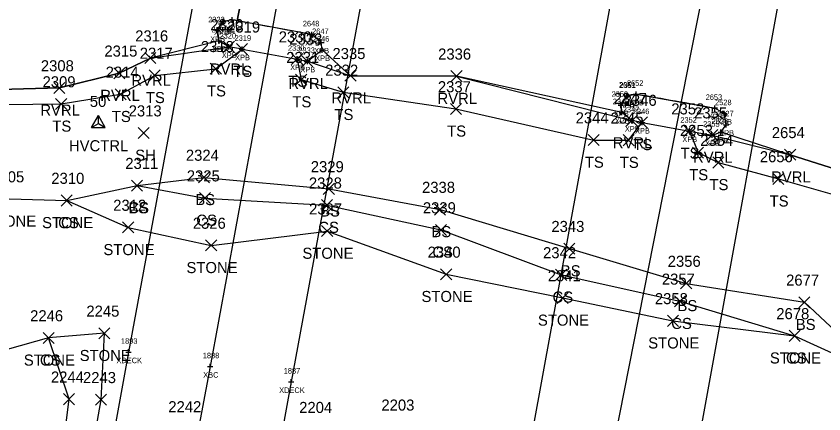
# Model space of a CAD drawing. Extents: x 1472022 to 1479249, y 777216 to 786527.
# Drawn here: x 1473550.5 to 1473696.2, y 779396.3 to 779468.1 of the extents above; entities that cross this region are included whole.
import ezdxf

# ---------------------------------------------------------------- set-up
doc = ezdxf.new("R2010")
doc.units = 0
for name, color, linetype in [('B_A', 7, 'Continuous'), ('B_I', 7, 'Continuous'), ('B_TIC', 7, 'Continuous'), ('BELB', 7, 'Continuous'), ('BSUBM', 7, 'Continuous'), ('C_A', 7, 'Continuous'), ('C_I', 7, 'Continuous'), ('CPSM', 7, 'Continuous'), ('L_A', 7, 'Continuous'), ('L_I', 7, 'Continuous'), ('L_TIC', 7, 'Continuous'), ('LASF', 7, 'Continuous'), ('LAWE', 7, 'Continuous'), ('LELB', 7, 'Continuous'), ('LSOGP', 7, 'Continuous')]:
    doc.layers.add(name, color=color, linetype=linetype)

msp = doc.modelspace()

# ---------------------------------------------------------------- linework, layer by layer
at = {"layer": 'B_TIC'}
for p, q in [((1473589.52, 779467.42), (1473589.6, 779467.42)), ((1473587.5, 779466.72), (1473587.58, 779466.72)), ((1473587.92, 779467.15), (1473587.99, 779467.15)), ((1473587.92, 779467.15), (1473587.99, 779467.15)), ((1473586.8, 779465.48), (1473586.87, 779465.48)), ((1473603.9, 779464.76), (1473603.97, 779464.76)), ((1473587.11, 779463.65), (1473587.19, 779463.65)), ((1473605.57, 779463.37), (1473605.64, 779463.37)), ((1473588.89, 779462.56), (1473588.97, 779462.56)), ((1473591.28, 779462.14), (1473591.36, 779462.14)), ((1473591.28, 779462.14), (1473591.36, 779462.14)), ((1473605.73, 779462), (1473605.8, 779462)), ((1473601.23, 779460.35), (1473601.3, 779460.35)), ((1473603.06, 779459.95), (1473603.14, 779459.95)), ((1473660.63, 779453.72), (1473660.71, 779453.72)), ((1473660.7, 779453.62), (1473660.78, 779453.62)), ((1473662.36, 779454.02), (1473662.43, 779454.02)), ((1473659.61, 779452.04), (1473659.69, 779452.04)), ((1473676.56, 779451.47), (1473676.63, 779451.47)), ((1473676.56, 779451.47), (1473676.63, 779451.47)), ((1473659.78, 779450.7), (1473659.86, 779450.7)), ((1473678.23, 779450.53), (1473678.31, 779450.53)), ((1473661.6, 779449.25), (1473661.67, 779449.25)), ((1473663.43, 779448.91), (1473663.51, 779448.91)), ((1473663.43, 779448.91), (1473663.51, 779448.91)), ((1473678.61, 779448.51), (1473678.68, 779448.51)), ((1473671.96, 779447.36), (1473672.04, 779447.36)), ((1473677.66, 779447.13), (1473677.74, 779447.13)), ((1473676.07, 779446.64), (1473676.14, 779446.64)), ((1473570.78, 779407.46), (1473570.86, 779407.46)), ((1473585.54, 779404.85), (1473585.61, 779404.85)), ((1473600.14, 779402.08), (1473600.21, 779402.08))]:
    msp.add_line(p, q, dxfattribs=at)
for points in [[(1473587.91, 779466.65), (1473587.91, 779467.65)], [(1473587.91, 779466.65), (1473587.91, 779467.65)], [(1473589.02, 779467.42), (1473590.02, 779467.42)], [(1473589.52, 779466.92), (1473589.52, 779467.92)], [(1473586.8, 779464.98), (1473586.8, 779465.98)], [(1473587, 779466.72), (1473588, 779466.72)], [(1473587.41, 779467.15), (1473588.41, 779467.15)], [(1473587.41, 779467.15), (1473588.41, 779467.15)], [(1473587.5, 779466.22), (1473587.5, 779467.22)], [(1473586.3, 779465.48), (1473587.3, 779465.48)], [(1473603.39, 779464.76), (1473604.39, 779464.76)], [(1473603.89, 779464.26), (1473603.89, 779465.26)], [(1473586.61, 779463.65), (1473587.61, 779463.65)], [(1473587.11, 779463.15), (1473587.11, 779464.15)], [(1473588.89, 779462.06), (1473588.89, 779463.06)], [(1473605.07, 779463.37), (1473606.07, 779463.37)], [(1473605.57, 779462.87), (1473605.57, 779463.87)], [(1473588.39, 779462.56), (1473589.39, 779462.56)], [(1473590.78, 779462.14), (1473591.78, 779462.14)], [(1473590.78, 779462.14), (1473591.78, 779462.14)], [(1473591.28, 779461.64), (1473591.28, 779462.64)], [(1473591.28, 779461.64), (1473591.28, 779462.64)], [(1473605.22, 779462), (1473606.22, 779462)], [(1473605.72, 779461.5), (1473605.72, 779462.5)], [(1473600.72, 779460.35), (1473601.72, 779460.35)], [(1473601.22, 779459.85), (1473601.22, 779460.85)], [(1473603.06, 779459.45), (1473603.06, 779460.45)], [(1473602.56, 779459.95), (1473603.56, 779459.95)], [(1473660.63, 779453.22), (1473660.63, 779454.22)], [(1473662.35, 779453.52), (1473662.35, 779454.52)], [(1473660.13, 779453.72), (1473661.13, 779453.72)], [(1473660.2, 779453.62), (1473661.2, 779453.62)], [(1473660.7, 779453.12), (1473660.7, 779454.12)], [(1473661.85, 779454.02), (1473662.85, 779454.02)], [(1473659.11, 779452.04), (1473660.11, 779452.04)], [(1473659.61, 779451.54), (1473659.61, 779452.54)], [(1473676.06, 779451.47), (1473677.06, 779451.47)], [(1473676.06, 779451.47), (1473677.06, 779451.47)], [(1473676.56, 779450.97), (1473676.56, 779451.97)], [(1473676.56, 779450.97), (1473676.56, 779451.97)], [(1473659.28, 779450.7), (1473660.28, 779450.7)], [(1473659.78, 779450.2), (1473659.78, 779451.2)], [(1473677.73, 779450.53), (1473678.73, 779450.53)], [(1473678.23, 779450.03), (1473678.23, 779451.03)], [(1473661.09, 779449.25), (1473662.09, 779449.25)], [(1473661.59, 779448.75), (1473661.59, 779449.75)], [(1473662.93, 779448.91), (1473663.93, 779448.91)], [(1473662.93, 779448.91), (1473663.93, 779448.91)], [(1473663.43, 779448.41), (1473663.43, 779449.41)], [(1473663.43, 779448.41), (1473663.43, 779449.41)], [(1473678.1, 779448.51), (1473679.1, 779448.51)], [(1473678.6, 779448.01), (1473678.6, 779449.01)], [(1473671.46, 779447.36), (1473672.46, 779447.36)], [(1473671.96, 779446.86), (1473671.96, 779447.86)], [(1473676.07, 779446.14), (1473676.07, 779447.14)], [(1473677.16, 779447.13), (1473678.16, 779447.13)], [(1473677.66, 779446.63), (1473677.66, 779447.63)], [(1473675.57, 779446.64), (1473676.57, 779446.64)], [(1473570.78, 779406.96), (1473570.78, 779407.96)], [(1473570.28, 779407.46), (1473571.28, 779407.46)], [(1473585.03, 779404.85), (1473586.03, 779404.85)], [(1473585.53, 779404.35), (1473585.53, 779405.35)], [(1473599.63, 779402.08), (1473600.63, 779402.08)], [(1473600.13, 779401.58), (1473600.13, 779402.58)]]:
    msp.add_lwpolyline(points, dxfattribs=at)
at = {"layer": 'BELB'}
for points in [[(1473646.9, 779823.47), (1473635.72, 779761.4), (1473617.71, 779663.02), (1473604.51, 779591.79), (1473588.93, 779505.83), (1473570.78, 779407.46), (1473559.55, 779345.54)], [(1473663.54, 779820.45), (1473650.78, 779758.62), (1473632.81, 779660.5), (1473616.07, 779571.01), (1473603.54, 779503.11), (1473585.53, 779404.85), (1473573.79, 779342.6)], [(1473676.24, 779818.18), (1473665.15, 779756.22), (1473647.13, 779657.83), (1473630.64, 779568.27), (1473618.22, 779500.38), (1473600.13, 779402.08), (1473588.74, 779339.91)], [(1473632.64, 779331.64), (1473643.77, 779393.67), (1473661.77, 779492.35), (1473674.97, 779565.3), (1473690.2, 779649.78), (1473708.22, 779748.21)], [(1473648.23, 779328.95), (1473658.53, 779391.7), (1473677.73, 779489.35), (1473690.33, 779561.53), (1473706.17, 779646.87), (1473724.09, 779745.09)], [(1473662.07, 779326.37), (1473673.18, 779388.74), (1473691.04, 779487.09), (1473704.3, 779559.92), (1473719.46, 779644.73), (1473737.38, 779742.92)]]:
    msp.add_lwpolyline(points, dxfattribs=at)
at = {"layer": 'BSUBM'}
for points in [[(1473591.28, 779462.14), (1473601.22, 779460.35), (1473603.06, 779459.95), (1473605.72, 779462), (1473605.57, 779463.37), (1473603.89, 779464.76), (1473589.52, 779467.42), (1473587.91, 779467.15)], [(1473591.28, 779462.14), (1473588.89, 779462.56), (1473587.11, 779463.65), (1473586.8, 779465.48), (1473587.5, 779466.72), (1473587.91, 779467.15)], [(1473663.43, 779448.91), (1473661.59, 779449.25), (1473659.78, 779450.7), (1473659.61, 779452.04), (1473660.7, 779453.62), (1473660.63, 779453.72), (1473662.35, 779454.02), (1473676.56, 779451.47)], [(1473663.43, 779448.91), (1473671.96, 779447.36), (1473676.07, 779446.64), (1473677.66, 779447.13), (1473678.6, 779448.51), (1473678.23, 779450.53), (1473676.56, 779451.47)]]:
    msp.add_lwpolyline(points, dxfattribs=at)
at = {"layer": 'CPSM'}
for p, q in [((1473564.11, 779447.99), (1473565.36, 779450.15)), ((1473566.61, 779447.99), (1473565.36, 779450.15)), ((1473565.36, 779448.71), (1473565.36, 779450.15)), ((1473564.11, 779447.99), (1473565.36, 779448.71)), ((1473565.36, 779448.71), (1473565.36, 779448.71)), ((1473565.36, 779448.71), (1473566.61, 779447.99)), ((1473564.11, 779447.99), (1473566.61, 779447.99))]:
    msp.add_line(p, q, dxfattribs=at)
at = {"layer": 'L_TIC'}
for points in [[(1473587.89, 779461.56), (1473589.89, 779463.56)], [(1473589.89, 779461.56), (1473587.89, 779463.56)], [(1473590.28, 779461.14), (1473592.28, 779463.14)], [(1473592.28, 779461.14), (1473590.28, 779463.14)], [(1473573.75, 779459.53), (1473575.75, 779461.53)], [(1473575.75, 779459.53), (1473573.75, 779461.53)], [(1473600.22, 779459.35), (1473602.22, 779461.35)], [(1473602.22, 779459.35), (1473600.22, 779461.35)], [(1473602.06, 779458.95), (1473604.06, 779460.95)], [(1473604.06, 779458.95), (1473602.06, 779460.95)], [(1473568.13, 779456.8), (1473570.13, 779458.8)], [(1473570.13, 779456.8), (1473568.13, 779458.8)], [(1473585.54, 779457.61), (1473587.54, 779459.61)], [(1473587.54, 779457.61), (1473585.54, 779459.61)], [(1473574.52, 779456.41), (1473576.52, 779458.41)], [(1473576.52, 779456.41), (1473574.52, 779458.41)], [(1473600.94, 779455.64), (1473602.94, 779457.64)], [(1473602.94, 779455.64), (1473600.94, 779457.64)], [(1473609.84, 779456.35), (1473611.84, 779458.35)], [(1473611.84, 779456.35), (1473609.84, 779458.35)], [(1473628.96, 779456.26), (1473630.96, 779458.26)], [(1473630.96, 779456.26), (1473628.96, 779458.26)], [(1473557.32, 779454.14), (1473559.32, 779456.14)], [(1473559.32, 779454.14), (1473557.32, 779456.14)], [(1473568.37, 779452.99), (1473570.37, 779454.99)], [(1473570.37, 779452.99), (1473568.37, 779454.99)], [(1473608.53, 779453.35), (1473610.53, 779455.35)], [(1473610.53, 779453.35), (1473608.53, 779455.35)], [(1473557.64, 779451.25), (1473559.64, 779453.25)], [(1473559.64, 779451.25), (1473557.64, 779453.25)], [(1473628.86, 779450.36), (1473630.86, 779452.36)], [(1473630.86, 779450.36), (1473628.86, 779452.36)], [(1473660.59, 779448.25), (1473662.59, 779450.25)], [(1473662.59, 779448.25), (1473660.59, 779450.25)], [(1473662.43, 779447.91), (1473664.43, 779449.91)], [(1473664.43, 779447.91), (1473662.43, 779449.91)], [(1473670.96, 779446.36), (1473672.96, 779448.36)], [(1473672.96, 779446.36), (1473670.96, 779448.36)], [(1473572.51, 779446), (1473574.51, 779448)], [(1473574.51, 779446), (1473572.51, 779448)], [(1473675.07, 779445.64), (1473677.07, 779447.64)], [(1473677.07, 779445.64), (1473675.07, 779447.64)], [(1473653.71, 779444.74), (1473655.71, 779446.74)], [(1473655.71, 779444.74), (1473653.71, 779446.74)], [(1473660, 779444.71), (1473662, 779446.71)], [(1473662, 779444.71), (1473660, 779446.71)], [(1473672.52, 779442.48), (1473674.52, 779444.48)], [(1473674.52, 779442.48), (1473672.52, 779444.48)], [(1473689.14, 779442.08), (1473691.14, 779444.08)], [(1473691.14, 779442.08), (1473689.14, 779444.08)], [(1473676.18, 779440.69), (1473678.18, 779442.69)], [(1473678.18, 779440.69), (1473676.18, 779442.69)], [(1473583.4, 779437.99), (1473585.4, 779439.99)], [(1473585.4, 779437.99), (1473583.4, 779439.99)], [(1473687.03, 779437.73), (1473689.03, 779439.73)], [(1473689.03, 779437.73), (1473687.03, 779439.73)], [(1473571.34, 779436.52), (1473573.34, 779438.52)], [(1473573.34, 779436.52), (1473571.34, 779438.52)], [(1473571.34, 779436.52), (1473573.34, 779438.52)], [(1473573.34, 779436.52), (1473571.34, 779438.52)], [(1473605.93, 779435.93), (1473607.93, 779437.93)], [(1473607.93, 779435.93), (1473605.93, 779437.93)], [(1473558.65, 779433.83), (1473560.65, 779435.83)], [(1473560.65, 779433.83), (1473558.65, 779435.83)], [(1473558.65, 779433.83), (1473560.65, 779435.83)], [(1473560.65, 779433.83), (1473558.65, 779435.83)], [(1473583.57, 779434.27), (1473585.57, 779436.27)], [(1473585.57, 779434.27), (1473583.57, 779436.27)], [(1473605.59, 779432.98), (1473607.59, 779434.98)], [(1473607.59, 779432.98), (1473605.59, 779434.98)], [(1473626, 779432.2), (1473628, 779434.2)], [(1473628, 779432.2), (1473626, 779434.2)], [(1473569.73, 779428.96), (1473571.73, 779430.96)], [(1473571.73, 779428.96), (1473569.73, 779430.96)], [(1473605.62, 779428.3), (1473607.62, 779430.3)], [(1473607.62, 779428.3), (1473605.62, 779430.3)], [(1473626.15, 779428.51), (1473628.15, 779430.51)], [(1473628.15, 779428.51), (1473626.15, 779430.51)], [(1473584.71, 779425.72), (1473586.71, 779427.72)], [(1473586.71, 779425.72), (1473584.71, 779427.72)], [(1473649.33, 779425.14), (1473651.33, 779427.14)], [(1473651.33, 779425.14), (1473649.33, 779427.14)], [(1473627.1, 779420.5), (1473629.1, 779422.5)], [(1473629.1, 779420.5), (1473627.1, 779422.5)], [(1473647.83, 779420.4), (1473649.83, 779422.4)], [(1473649.83, 779420.4), (1473647.83, 779422.4)], [(1473670.38, 779418.85), (1473672.38, 779420.85)], [(1473672.38, 779418.85), (1473670.38, 779420.85)], [(1473648.11, 779416.23), (1473650.11, 779418.23)], [(1473650.11, 779416.23), (1473648.11, 779418.23)], [(1473669.26, 779415.63), (1473671.26, 779417.63)], [(1473671.26, 779415.63), (1473669.26, 779417.63)], [(1473691.72, 779415.45), (1473693.72, 779417.45)], [(1473693.72, 779415.45), (1473691.72, 779417.45)], [(1473668, 779412.11), (1473670, 779414.11)], [(1473670, 779412.11), (1473668, 779414.11)], [(1473555.37, 779409.02), (1473557.37, 779411.02)], [(1473557.37, 779409.02), (1473555.37, 779411.02)], [(1473555.37, 779409.02), (1473557.37, 779411.02)], [(1473557.37, 779409.02), (1473555.37, 779411.02)], [(1473565.45, 779409.85), (1473567.45, 779411.85)], [(1473567.45, 779409.85), (1473565.45, 779411.85)], [(1473689.95, 779409.4), (1473691.95, 779411.4)], [(1473691.95, 779409.4), (1473689.95, 779411.4)], [(1473689.95, 779409.4), (1473691.95, 779411.4)], [(1473691.95, 779409.4), (1473689.95, 779411.4)], [(1473559.06, 779397.96), (1473561.06, 779399.96)], [(1473561.06, 779397.96), (1473559.06, 779399.96)], [(1473564.84, 779397.86), (1473566.84, 779399.86)], [(1473566.84, 779397.86), (1473564.84, 779399.86)]]:
    msp.add_lwpolyline(points, dxfattribs=at)
at = {"layer": 'LASF'}
for points in [[(1473473.27, 779398.69), (1473490.14, 779416.95), (1473498.08, 779421.83), (1473506.81, 779422.34), (1473517.64, 779423.49), (1473523.38, 779426.73), (1473532.1, 779433.42), (1473538.27, 779434.84), (1473549.37, 779435.1), (1473559.65, 779434.83), (1473570.73, 779429.96), (1473585.71, 779426.72), (1473606.62, 779429.3), (1473628.1, 779421.5), (1473649.11, 779417.23), (1473669, 779413.11), (1473690.95, 779410.4), (1473712.68, 779400.49)], [(1473633.09, 779342.06), (1473637.36, 779354.76), (1473634.83, 779370.15), (1473634.39, 779386.13), (1473619.75, 779393.9), (1473604.91, 779393.47), (1473602.82, 779381.23), (1473597.4, 779362.46), (1473593.63, 779347.94), (1473579.62, 779350.93), (1473559.31, 779355.6), (1473561.08, 779365.73), (1473563.08, 779383.25), (1473565.84, 779398.86), (1473566.45, 779410.85), (1473556.37, 779410.02), (1473539.02, 779405.15), (1473523.92, 779401.84), (1473511.03, 779390.76), (1473502.06, 779373.78), (1473492.39, 779361.71)]]:
    msp.add_lwpolyline(points, dxfattribs=at)
at = {"layer": 'LAWE'}
for points in [[(1473463.64, 779459.86), (1473474.22, 779451.75), (1473490.1, 779450.63), (1473502.38, 779450.61), (1473513.03, 779446.48), (1473521.87, 779448.87), (1473523.28, 779449.82), (1473531, 779452.15), (1473543.2, 779454.75), (1473558.32, 779455.14), (1473569.13, 779457.8), (1473574.75, 779460.53), (1473588.89, 779462.56)], [(1473603.06, 779459.95), (1473610.84, 779457.35), (1473629.96, 779457.26), (1473661.59, 779449.25)], [(1473676.07, 779446.64), (1473690.14, 779443.08), (1473702.13, 779439.28), (1473717.49, 779433.42), (1473726.6, 779424.72), (1473742.11, 779423.68), (1473761.32, 779420.04), (1473781.68, 779418.82), (1473795.31, 779417.72)]]:
    msp.add_lwpolyline(points, dxfattribs=at)
at = {"layer": 'LELB'}
for points in [[(1473523.26, 779448.59), (1473531.84, 779450.04), (1473543.26, 779452.12), (1473558.64, 779452.25), (1473569.37, 779453.99), (1473575.52, 779457.41), (1473586.54, 779458.61), (1473591.28, 779462.14)], [(1473601.22, 779460.35), (1473601.94, 779456.64), (1473609.53, 779454.35), (1473629.86, 779451.36), (1473654.71, 779445.74), (1473661, 779445.71), (1473663.43, 779448.91)], [(1473671.96, 779447.36), (1473673.52, 779443.48), (1473677.18, 779441.69), (1473688.03, 779438.73), (1473702.75, 779434.5), (1473716.59, 779429.46), (1473726.14, 779421.28), (1473742.15, 779420.24), (1473760.21, 779417.42), (1473781.41, 779415.7), (1473794.44, 779413.22)], [(1473572.34, 779437.52), (1473584.4, 779438.99), (1473606.93, 779436.93), (1473627, 779433.2), (1473650.33, 779426.14), (1473671.38, 779419.85), (1473692.72, 779416.45), (1473704.93, 779405.04), (1473712.68, 779400.49)], [(1473559.65, 779434.83), (1473572.34, 779437.52), (1473584.57, 779435.27), (1473606.59, 779433.98), (1473627.15, 779429.51), (1473648.83, 779421.4), (1473670.26, 779416.63), (1473690.95, 779410.4)], [(1473554.9, 779337.02), (1473552.17, 779346.9), (1473553.8, 779354.39), (1473554.89, 779367.06), (1473558.14, 779383.69), (1473560.06, 779398.96), (1473556.37, 779410.02)]]:
    msp.add_lwpolyline(points, dxfattribs=at)
at = {"layer": 'LSOGP'}
for points in [[(1473634.56, 779697.97), (1473590.42, 779467.25), (1473589.52, 779467.42), (1473588.72, 779467.28), (1473587.91, 779467.15), (1473587.5, 779466.72), (1473586.8, 779465.48), (1473586.95, 779464.57), (1473587.11, 779463.65), (1473574.75, 779460.53), (1473569.13, 779457.8), (1473558.32, 779455.14), (1473543.2, 779454.75)], [(1473702.13, 779439.28), (1473690.14, 779443.08), (1473677.66, 779447.13), (1473678.13, 779447.82), (1473678.6, 779448.51), (1473678.42, 779449.52), (1473678.23, 779450.53), (1473677.39, 779451), (1473676.56, 779451.47), (1473675.67, 779451.63), (1473674.78, 779451.79), (1473673.89, 779451.95), (1473673, 779452.11), (1473672.12, 779452.27), (1473671.23, 779452.43), (1473670.34, 779452.59), (1473669.45, 779452.74), (1473668.57, 779452.9), (1473667.68, 779453.06), (1473666.79, 779453.22), (1473665.9, 779453.38), (1473665.02, 779453.54), (1473664.13, 779453.7), (1473663.24, 779453.86), (1473662.35, 779454.02), (1473661.49, 779453.87), (1473660.63, 779453.72), (1473659.61, 779452.04), (1473659.78, 779450.7), (1473629.96, 779457.26), (1473610.84, 779457.35), (1473605.72, 779462), (1473605.57, 779463.37), (1473604.73, 779464.06), (1473603.89, 779464.76), (1473602.99, 779464.92), (1473602.1, 779465.09), (1473601.2, 779465.25), (1473600.3, 779465.42), (1473599.4, 779465.59), (1473598.5, 779465.75), (1473597.6, 779465.92), (1473596.71, 779466.09), (1473595.81, 779466.25), (1473594.91, 779466.42), (1473594.01, 779466.58), (1473593.11, 779466.75), (1473592.22, 779466.92), (1473591.32, 779467.08), (1473590.42, 779467.25), (1473634.56, 779697.97)]]:
    msp.add_lwpolyline(points, dxfattribs=at)

# ---------------------------------------------------------------- texts
at = {"layer": 'B_A'}
for s, p in [('XPB', (1473586.65, 779465.15)), ('XPB', (1473586.65, 779465.15)), ('XPB', (1473588.26, 779465.42)), ('XPB', (1473585.53, 779463.48)), ('XPB', (1473586.23, 779464.72)), ('XPB', (1473602.63, 779462.76)), ('XPB', (1473585.84, 779461.65)), ('XPB', (1473587.62, 779460.56)), ('XPB', (1473604.3, 779461.37)), ('XPB', (1473590.02, 779460.14)), ('XPB', (1473590.02, 779460.14)), ('XPB', (1473604.46, 779460)), ('XPB', (1473599.96, 779458.35)), ('XPB', (1473601.79, 779457.95)), ('XPB', (1473659.36, 779451.72)), ('XPB', (1473661.09, 779452.02)), ('XPB', (1473659.43, 779451.62)), ('XPB', (1473658.34, 779450.04)), ('XPB', (1473675.29, 779449.47)), ('XPB', (1473675.29, 779449.47)), ('XPB', (1473658.51, 779448.7)), ('XPB', (1473676.97, 779448.53)), ('XPB', (1473660.33, 779447.25)), ('XPB', (1473662.16, 779446.91)), ('XPB', (1473662.16, 779446.91)), ('XPB', (1473677.34, 779446.51)), ('XPB', (1473670.69, 779445.36)), ('XPB', (1473674.8, 779444.64)), ('XPB', (1473676.39, 779445.13)), ('XDECK', (1473568.62, 779405.46)), ('XBC', (1473584.27, 779402.85)), ('XDECK', (1473597.97, 779400.08))]:
    msp.add_text(s, height=1, dxfattribs=at).set_placement(p)
at = {"layer": 'B_I'}
for s, p in [('2322', (1473585.17, 779466.98)), ('2648', (1473602.24, 779466.26)), ('2321', (1473585.76, 779465.15)), ('2647', (1473603.91, 779464.87)), ('2320', (1473587.22, 779464.06)), ('2319', (1473589.93, 779463.64)), ('2319', (1473589.93, 779463.64)), ('2646', (1473604.04, 779463.5)), ('2330', (1473599.55, 779461.85)), ('2333', (1473601.43, 779461.45)), ('2651', (1473659.26, 779455.22)), ('2351', (1473659.35, 779455.12)), ('2652', (1473660.7, 779455.52)), ('2350', (1473657.93, 779453.54)), ('2349', (1473658.14, 779452.2)), ('2653', (1473674.9, 779452.97)), ('2653', (1473674.9, 779452.97)), ('2528', (1473676.6, 779452.03)), ('2347', (1473659.96, 779450.75)), ('2346', (1473661.77, 779450.41)), ('2346', (1473661.77, 779450.41)), ('2352', (1473670.33, 779448.86)), ('2527', (1473676.97, 779450.01)), ('2355', (1473674.44, 779448.14)), ('2526', (1473676, 779448.63)), ('1893', (1473569.43, 779408.96)), ('1888', (1473584.19, 779406.35)), ('1887', (1473598.79, 779403.58))]:
    msp.add_text(s, height=1, dxfattribs=at).set_placement(p)
at = {"layer": 'C_A'}
msp.add_text('HVCTRL', height=2, dxfattribs=at).set_placement((1473560.05, 779443.71))
at = {"layer": 'C_I'}
msp.add_text('50', height=2, dxfattribs=at).set_placement((1473563.81, 779451.71))
at = {"layer": 'L_A'}
for s, p in [('RVRL', (1473585.46, 779457.56)), ('TS', (1473589.69, 779457.14)), ('RVRL', (1473571.31, 779455.53)), ('TS', (1473599.63, 779455.35)), ('TS', (1473584.95, 779453.61)), ('RVRL', (1473599.62, 779454.95)), ('RVRL', (1473565.7, 779452.8)), ('TS', (1473573.93, 779452.41)), ('RVRL', (1473607.41, 779452.35)), ('RVRL', (1473626.52, 779452.26)), ('TS', (1473600.35, 779451.64)), ('RVRL', (1473554.89, 779450.14)), ('TS', (1473607.94, 779449.35)), ('TS', (1473567.78, 779448.99)), ('TS', (1473557.05, 779447.25)), ('TS', (1473628.27, 779446.36)), ('RVRL', (1473658.16, 779444.25)), ('TS', (1473661.84, 779443.91)), ('SH', (1473572, 779442)), ('TS', (1473670.37, 779442.36)), ('TS', (1473653.11, 779440.74)), ('TS', (1473659.41, 779440.71)), ('RVRL', (1473672.63, 779441.64)), ('TS', (1473671.93, 779438.48)), ('RVRL', (1473686.71, 779438.08)), ('TS', (1473675.59, 779436.69)), ('BS', (1473582.84, 779433.99)), ('TS', (1473686.44, 779433.73)), ('CS', (1473570.78, 779432.52)), ('BS', (1473570.78, 779432.52)), ('BS', (1473605.37, 779431.93)), ('CS', (1473583.02, 779430.27)), ('STONE', (1473544.92, 779430.1)), ('STONE', (1473555.2, 779429.83)), ('CS', (1473558.1, 779429.83)), ('CS', (1473605.03, 779428.98)), ('BS', (1473625.44, 779428.2)), ('STONE', (1473566.27, 779424.96)), ('CS', (1473625.6, 779424.51)), ('STONE', (1473602.16, 779424.3)), ('STONE', (1473581.25, 779421.72)), ('BS', (1473648.77, 779421.14)), ('STONE', (1473623.64, 779416.5)), ('CS', (1473647.28, 779416.4)), ('BS', (1473669.82, 779414.85)), ('STONE', (1473644.65, 779412.23)), ('CS', (1473668.7, 779411.63)), ('BS', (1473691.16, 779411.45)), ('STONE', (1473664.54, 779408.11)), ('STONE', (1473561.99, 779405.85)), ('STONE', (1473551.91, 779405.02)), ('CS', (1473554.81, 779405.02)), ('STONE', (1473686.49, 779405.4)), ('CS', (1473689.39, 779405.4))]:
    msp.add_text(s, height=2, dxfattribs=at).set_placement(p)
at = {"layer": 'L_I'}
for s, p in [('2320', (1473585.54, 779465.56)), ('2319', (1473588.58, 779465.14)), ('2316', (1473572, 779463.53)), ('2330', (1473597.88, 779463.35)), ('2333', (1473599.8, 779462.95)), ('2318', (1473583.84, 779461.61)), ('2315', (1473566.44, 779460.8)), ('2317', (1473572.82, 779460.41)), ('2331', (1473599.24, 779459.64)), ('2335', (1473607.58, 779460.35)), ('2336', (1473626.64, 779460.26)), ('2308', (1473554.98, 779458.14)), ('2314', (1473566.67, 779456.99)), ('2332', (1473606.27, 779457.35)), ('2309', (1473555.29, 779455.25)), ('2337', (1473626.6, 779454.36)), ('2347', (1473658.33, 779452.25)), ('2346', (1473660.11, 779451.91)), ('2313', (1473570.82, 779450)), ('2352', (1473668.7, 779450.36)), ('2355', (1473672.81, 779449.64)), ('2344', (1473651.45, 779448.74)), ('2345', (1473657.74, 779448.71)), ('2353', (1473670.26, 779446.48)), ('2654', (1473686.83, 779446.08)), ('2354', (1473673.92, 779444.69)), ('2324', (1473581.14, 779441.99)), ('2311', (1473570.21, 779440.52)), ('2311', (1473570.21, 779440.52)), ('2656', (1473684.67, 779441.73)), ('2329', (1473603.67, 779439.93)), ('2305', (1473546.03, 779438.1)), ('2310', (1473556.87, 779437.83)), ('2310', (1473556.87, 779437.83)), ('2325', (1473581.31, 779438.27)), ('2328', (1473603.33, 779436.98)), ('2338', (1473623.74, 779436.2)), ('2312', (1473568.03, 779432.96)), ('2327', (1473603.36, 779432.3)), ('2339', (1473623.89, 779432.51)), ('2326', (1473582.39, 779429.72)), ('2343', (1473647.07, 779429.14)), ('2340', (1473624.75, 779424.5)), ('2342', (1473645.57, 779424.4)), ('2356', (1473668.06, 779422.85)), ('2341', (1473646.42, 779420.23)), ('2357', (1473667, 779419.63)), ('2677', (1473689.41, 779419.45)), ('2358', (1473665.74, 779416.11)), ('2246', (1473553.05, 779413.02)), ('2246', (1473553.05, 779413.02)), ('2245', (1473563.19, 779413.85)), ('2678', (1473687.64, 779413.4)), ('2678', (1473687.64, 779413.4)), ('2244', (1473556.8, 779401.96)), ('2243', (1473562.58, 779401.86)), ('2203', (1473616.41, 779396.9)), ('2242', (1473577.97, 779396.6)), ('2204', (1473601.58, 779396.47))]:
    msp.add_text(s, height=2, dxfattribs=at).set_placement(p)

doc.saveas('drawing.dxf')
